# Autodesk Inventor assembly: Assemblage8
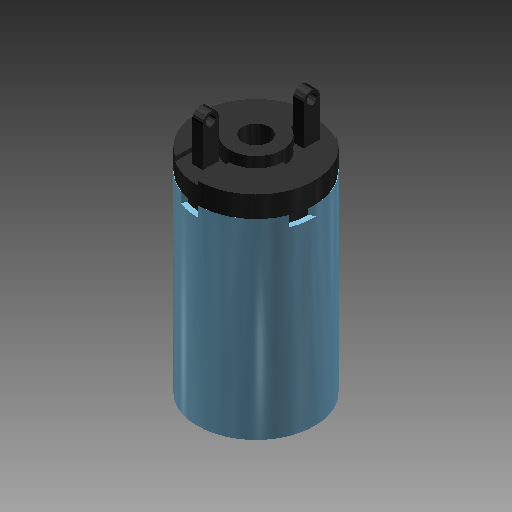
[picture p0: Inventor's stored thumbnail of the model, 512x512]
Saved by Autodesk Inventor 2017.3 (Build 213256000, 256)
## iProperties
Created: 2007-12
Part Number: Assemblage8
Material: Générique
Document SubType Name: Assembly
Designer: ficho
Author: ficho
Sending System: SolidWorks 2009
Last Author: christophe
Last Saved: 2011-02-10
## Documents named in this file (3)
- G:\travail\année 2019-2020\réforme\toussaint\Serrure biométrique SET\Documentations_pedagogique\Modelisation_Solidworks\Assemblage8.iam
- G:\travail\année 2019-2020\réforme\toussaint\Serrure biométrique SET\Documentations_pedagogique\Modelisation_Solidworks\piece 33.ipt
- G:\travail\année 2019-2020\réforme\toussaint\Serrure biométrique SET\Documentations_pedagogique\Modelisation_Solidworks\piece32.ipt
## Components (2 placed, 2 different names)
1. piece 33:1
2. piece32:1
